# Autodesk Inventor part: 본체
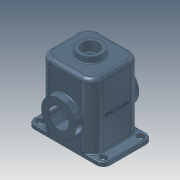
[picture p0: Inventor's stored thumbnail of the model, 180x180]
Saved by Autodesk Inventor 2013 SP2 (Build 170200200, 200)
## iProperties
Company: 한국ATC센터
Created: 2014-10
Part Number: 본체
Document SubType Name: Modeling
Designer: 한국ATC센터
Density: 2.71 g/cm^3
Material: 알루미늄 6061
Mass: 3285.46 g
Surface Area: 2358.49 cm^2
Volume: 1212.35 cm^3
Author: KYOUNG IL JANG
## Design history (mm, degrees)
sketch "스케치1"
  geometry: L1 (-70, 65)-(70, 65); L2 (70, 65)-(70, -65); L3 (70, -65)-(-70, -65); L4 (-70, -65)-(-70, 65); 3 further points
  constraints: 8 end point, 2 midpoint, 2 parallel, 1 horizontal, 1 horizontal alignment, 1 perpendicular, 1 vertical alignment
  dimensions: "d0" = 140 distance of L2.end L3.end; "d68" = 130 distance of L3.end L1.start
extrude "돌출1" new body sketch "스케치1" distance "d1" = 180; taper "d2" = 0 deg
fillet "모깎기1" dims "d3" = 20
feature "쉘1" dims "d4" = 10
sketch "스케치2"
  geometry: L1 (-70, 45)-(-70, -45) reference; L2 (-50, -65)-(-82, -65); L3 (-82, 65)-(-50, 65); L4 (-85, 57)-(-82, 57); L5 (-82, 41)-(-85, 41); L6 (-100, 47)-(-100, -47); A1 r 20 centre (-50, 45) between (-50, 65) and (-70, 45) reference; A2 r 20 centre (-50, -45) between (-70, -45) and (-50, -65) reference; A3 r 8 centre (-82, 49) between (-82, 41) and (-82, 57); A4 r 8 centre (-85, 49) between (-85, 57) and (-85, 41); A5 r 18 centre (-82, 47) between (-82, 65) and (-100, 47); A6 r 18 centre (-82, -47) between (-100, -47) and (-82, -65); 1 further point
  constraints: 10 end point, 9 tangent, 8 point on circle, 4 centre point, 2 parallel, 2 perpendicular, 1 equal radius
  dimensions: "d6" = 49 vertical distance of point (0, 0) A3.centre; "d8" = 16 distance between parallel lines of L4 L5; "d64" = 18 radius of A5; "d65" = 12 distance from line of A3.centre L1; "d66" = 30 distance between parallel lines of L6 L1; "d67" = 3 distance of A4.centre A3.centre
extrude "돌출2" join sketch "스케치2" distance "d9" = 10; taper "d10" = 0 deg
extrude "돌출3" cut sketch "스케치2" stored distance "d11" = 10; taper "d12" = 0 deg
sketch "스케치3"
  geometry: L1 (-65, 0)-(-65, 180) reference; L2 (-55, 0)-(-55, 170) reference; L3 (-83, 75)-(-51, 75); L4 (45, 0)-(-45, 0) reference; L5 (-83, 75)-(-83, 120.5); L6 (-83, 120.5)-(-55, 120.5); L7 (-55, 120.5)-(-51, 116.5); L8 (-51, 116.5)-(-51, 75); 2 further points
  constraints: 10 end point, 4 perpendicular, 1 point on line
  dimensions: "d13" = 75 distance between parallel lines of L3 L4; "d14" = 18 distance from line of L1 L3.start; "d15" = 4 distance from line of L3.end L2; "d16" = 91 diameter of L6 L3; "d17" = 135 deg angle of L7 L2
revolve "회전1" sketch "스케치3" stored, may be unused: angle "d18" = 90 deg
sketch "스케치4"
  geometry: C1 r 45.5 at (0, 0) reference; 2 further points
  constraints: 1 vertical alignment
  dimensions: "d19" = 35 distance of C1.centre point (0, 35)
hole "구멍1" sketch "스케치4" at (0, 35) diameter "d20" = 3.459; stored, may be unused: countersink angle "d24" = 90 deg, drill point angle "d26" = 118 deg; dims "d21" = 13, "d22" = 4, "d23" = 2, "d25" = 16
fillet "모깎기2" dims "d30" = 3
hole "구멍2" diameter "d33" = 52; stored, may be unused: countersink angle "d37" = 90 deg, drill point angle "d39" = 118 deg; dims "d31" = 10, "d32" = 10, "d34" = 13, "d35" = 4, "d36" = 2, "d38" = 16
sketch "스케치5"
  geometry: C1 r 31 at (0, 0); 1 further point
  constraints: 1 centre point, 1 coincident
  dimensions: "d40" = 62 diameter of C1
extrude "돌출4" join sketch "스케치5" distance "d41" = 15; taper "d42" = 0 deg
hole "구멍3" diameter "d45" = 43; stored, may be unused: countersink angle "d49" = 90 deg, drill point angle "d51" = 118 deg; dims "d43" = 10, "d44" = 10, "d46" = 13, "d47" = 4, "d48" = 2, "d50" = 16
fillet "모깎기3" dims "d52" = 3
fillet "모깎기4" dims "d53" = 3
chamfer "모따기1" distance "d55" = 1; stored, may be unused: second distance "d56" = 2, angle "d57" = 45 deg
sketch "스케치6"
  geometry: 2 further points
  constraints: 1 vertical alignment, 1 other
  dimensions: "d71" = 90 distance of point (0, 0) point (0, 90)
feature "엠보싱2" sketch "스케치6" dims "d0" = 140, "d68" = 130, "d72" = 1, "d73" = 0
fillet "모깎기6" dims "d74" = 10
sketch "스케치7"
  geometry: C1 r 15 at (0, 0); C2 r 21.5 at (0, 0) reference; C3 r 25 at (0, 0); 1 further point
  constraints: 2 centre point, 2 coincident
  dimensions: "d61" = 30 diameter of C1; "d75" = 50 diameter of C3
extrude "돌출5" join sketch "스케치7" distance "d62" = 10; taper "d63" = 0 deg
feature "면 이동1" dims "d76" = 1
fillet "모깎기7" dims "d77" = 3
node "솔리드1"
mirror "대칭1"
mirror "대칭2"
pattern_circular "원형 패턴1" dims angle "d28" = 360 deg
mirror "대칭3"
